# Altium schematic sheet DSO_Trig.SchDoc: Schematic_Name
size A4; CompanyName: University of Melbourne; Engineer: Your Name Here; DocumentNumber: 1; Revision: 0.1; SheetNumber: 1; SheetTotal: 1; Title_Project: Project_Title; StudentNo: Student No.
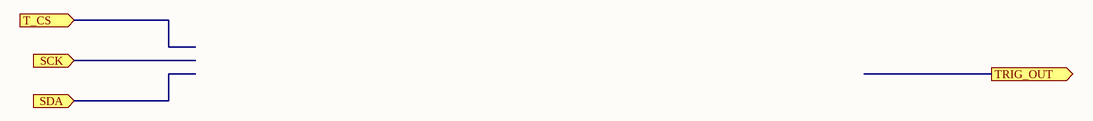
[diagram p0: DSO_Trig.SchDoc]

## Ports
SCK (in), SDA (in), T_CS (in), TRIG_OUT (out)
